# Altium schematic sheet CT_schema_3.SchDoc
size 287 x 163 mm
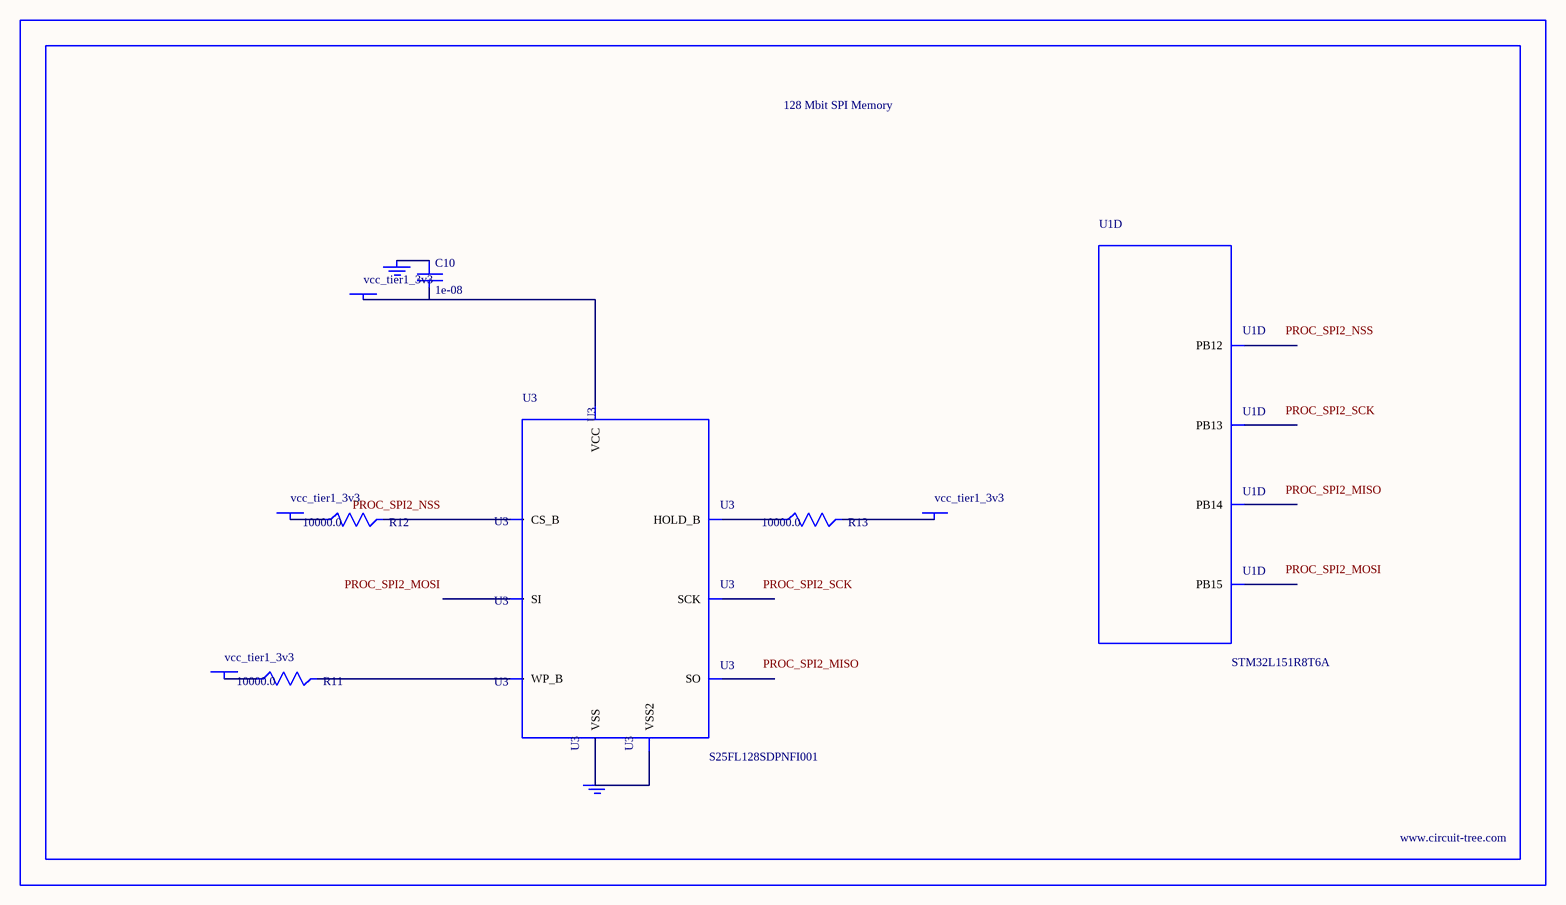
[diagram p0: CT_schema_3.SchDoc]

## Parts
BORDER2  (no value)
C10  1e-08  [C0402]
GND_INSTANCE_2_0  (no value)
GND_INSTANCE_2_1  (no value)
POWER_INSTANCE_2_0  vcc_tier1_3v3
POWER_INSTANCE_2_1  vcc_tier1_3v3
POWER_INSTANCE_2_2  vcc_tier1_3v3
POWER_INSTANCE_2_3  vcc_tier1_3v3
R11  10000.0  [R0603]
R12  10000.0  [R0603]
R13  10000.0  [R0603]
U1  STM32L151R8T6A  [LQFP64]  (part D of 7)
U3  S25FL128SDPNFI001  [WNG008]

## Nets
NetC10_1: C10.1 GND_INSTANCE_2_0.0(GND)
NetC10_2: C10.2 POWER_INSTANCE_2_3.0(PWR) U3.8(VCC)
NetGND_INSTANCE_2_1_0: GND_INSTANCE_2_1.0(GND) U3.4(VSS) U3.PAD(VSS2)
NetPOWER_INSTANCE_2_0_0: POWER_INSTANCE_2_0.0(PWR) R12.1
NetPOWER_INSTANCE_2_1_0: POWER_INSTANCE_2_1.0(PWR) R11.1
NetPOWER_INSTANCE_2_2_0: POWER_INSTANCE_2_2.0(PWR) R13.2
NetR11_2: R11.2 U3.3(WP_B)
NetR12_2: R12.2 U3.1(CS_B)
NetR13_1: R13.1 U3.7(HOLD_B)

Not connected (* = marked no-connect by the designer): U1 33(PB12) 34(PB13) 35(PB14) 36(PB15); U3 2(SO) 5(SI) 6(SCK)

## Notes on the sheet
- Labels drawn without touching a wire or pin: PROC_SPI2_MISO, PROC_SPI2_MOSI, PROC_SPI2_NSS, PROC_SPI2_SCK

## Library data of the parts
BORDER2 = BORDER_PAGE2
C10 = C0402C103K3RAC
GND_INSTANCE_2_0 GND_INSTANCE_2_1 = GND
POWER_INSTANCE_2_0-POWER_INSTANCE_2_3 = PWR
R11-R13 = RC0603JR-0710KL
